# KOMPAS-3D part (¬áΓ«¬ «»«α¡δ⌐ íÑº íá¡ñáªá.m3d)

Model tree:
1. Эскиз:11
2. Операция выдавливания:8
     Расстояние 1 = 1.5; Расстояние 2 = 2
3. Эскиз:19
4. Операция выдавливания:11
     Расстояние 1 = 12; Расстояние 2 = 2
5. Эскиз:20
6. Смещенная плоскость:1
     Расстояние = 2.5
7. Эскиз:43
8. Операция выдавливания:19
     Расстояние 1 = 10
9. Вырезать элемент выдавливания:23
     Расстояние 2 = 0.5; Расстояние 1 = 5.5
10. Эскиз:44
11. Вырезать элемент выдавливания:24
     Расстояние 2 = 0.5; Расстояние 1 = 0.5
12. Эскиз:45
13. Вырезать элемент выдавливания:25
     Расстояние 2 = 0.5; Расстояние 1 = 0.5
14. Эскиз:46
15. Операция выдавливания:20
     Расстояние 1 = 3.5
16. Эскиз:47
17. Вырезать элемент выдавливания:26
     Расстояние 2 = 0.5; Расстояние 1 = 5.5
18. Эскиз:48
19. Вырезать элемент выдавливания:27
     Расстояние 2 = 0.5; Расстояние 1 = 5
20. Скругление:14
     Радиус = 0.5
21. Скругление:15
     Радиус = 0.1
22. Скругление:16
     Радиус = 0.1
23. Фаска:3
     Угол = 45; Длина 1 = 0.5; Длина 2 = 0.5
24. Эскиз:49
25. Вырезать элемент выдавливания:28
     Расстояние 2 = 0.5; Расстояние 1 = 2
26. Скругление:17
     Радиус = 1
27. Скругление:18
     Радиус = 1
28. Эскиз:50
29. Операция выдавливания:21
     Расстояние 1 = 1
30. Эскиз:51
31. Операция выдавливания:22
     Расстояние 1 = 0.5
32. Скругление:19
     Радиус = 0.1
33. Скругление:20
     Радиус = 0.1
34. Массив по концентрической сетке:5  (with: Вырезать элемент выдавливания:28, Скругление:17, Скругление:18, Операция выдавливания:21, Операция выдавливания:22, Скругление:19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)  (labels: Экземпляр ( 1, 1 ); Экземпляр ( 1, 2 ); Экземпляр ( 1, 3 ); Экземпляр ( 1, 4 ))
     N 2 = 6; Шаг 2 = 360; Номер 2 = 1
35. Эскиз:52
36. Вырезать элемент выдавливания:29
     Расстояние 1 = 2
37. Эскиз:53
38. Вырезать элемент выдавливания:30
     Расстояние 1 = 13.5

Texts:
  Каток опорный без бандажа
  Сплав АЛ8  ГОСТ 1583-93
  stalker61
